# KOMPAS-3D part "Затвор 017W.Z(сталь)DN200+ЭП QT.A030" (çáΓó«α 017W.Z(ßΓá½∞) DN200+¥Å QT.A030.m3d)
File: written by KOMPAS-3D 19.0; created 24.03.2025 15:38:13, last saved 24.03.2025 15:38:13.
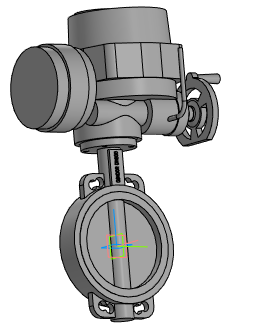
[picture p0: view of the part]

Document properties: Полное имя файла: Затвор 017W.Z(сталь) DN200+ЭП QT.A030.a3d

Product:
- Part/product: Затвор 017W.Z(сталь)DN200+ЭП QT.A030
    Масса: 134.191

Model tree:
1. Операция без истории:1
